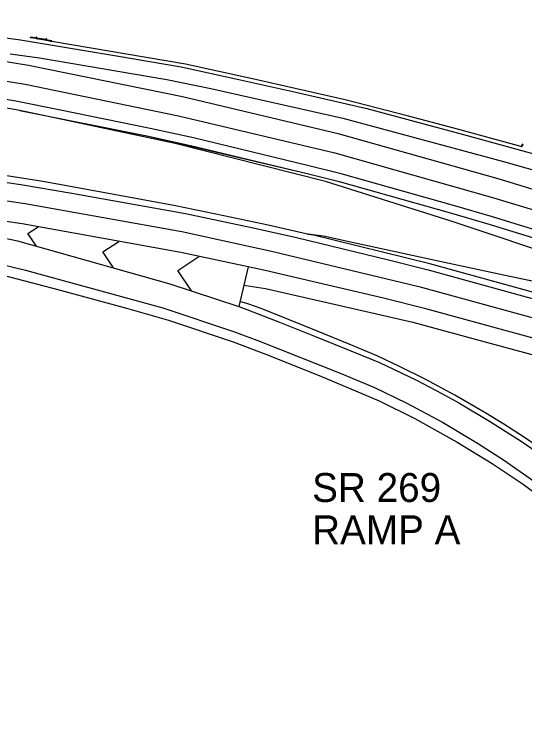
# Model space of a CAD drawing. Extents: x 1855721 to 1876784, y 662259 to 674089.
# Drawn here: x 1874026.9 to 1874344.5, y 669790 to 670235.9 of the extents above; entities that cross this region are included whole.
import ezdxf

# ---------------------------------------------------------------- set-up
doc = ezdxf.new("R2010")
doc.units = 0
for name, color, linetype in [('_CIVIL_CONSTRUCTION', 7, 'Continuous'), ('GE_X_Alignment_100_Bearings', 7, 'Continuous'), ('GE_X_Alignment_100_Cardinal_Points', 7, 'Continuous'), ('GE_X_Alignment_100_Curve_Data', 7, 'Continuous'), ('GE_X_Alignment_100_Distances', 7, 'Continuous'), ('RD_P_Anchor_Assembly', 7, 'Continuous'), ('RD_P_GR_Rt', 7, 'Continuous'), ('SC_Scratch1', 7, 'Continuous')]:
    doc.layers.add(name, color=color, linetype=linetype)

msp = doc.modelspace()

# ---------------------------------------------------------------- linework, layer by layer
at = {"layer": '_CIVIL_CONSTRUCTION'}
msp.add_line((1874172.51, 670078.73), (1874166.57, 670053.98), dxfattribs=at)
for points in [[(1874024.21, 670211.44), (1874042.5, 670208.83), (1874121.86, 670195.43), (1874149.23, 670189.87), (1874231.37, 670171.25), (1874331.43, 670144.39), (1874360.53, 670136.03), (1874385.65, 670128.8), (1874405.39, 670122.67), (1874479.05, 670099.61), (1874543.69, 670077.25), (1874566.95, 670068.66), (1874616.63, 670049.72), (1874641.2, 670039.89), (1874701.25, 670015)], [(1874008.89, 670082.71), (1874033.84, 670076.62), (1874119.31, 670053.19), (1874163.98, 670038.32), (1874179.51, 670032.41), (1874230.65, 670012.2), (1874251.08, 670003.56), (1874270.71, 669994.19), (1874293.29, 669982.11), (1874315.24, 669969.02), (1874331.35, 669958.59), (1874347.94, 669947.07), (1874364.69, 669934.66), (1874379.33, 669923.11), (1874391.51, 669912.94), (1874407.55, 669898.63), (1874421.29, 669885.42), (1874437.51, 669868.5), (1874447.7, 669857.03), (1874462.1, 669839.52), (1874471.05, 669827.84), (1874485.09, 669808.34), (1874501.91, 669783.12)], [(1874656.55, 669923.15), (1874616.51, 669940.01), (1874596.5, 669948.2), (1874520.89, 669977.13), (1874502.63, 669983.85), (1874434.3, 670008.02), (1874411.92, 670015.44), (1874387.2, 670023.2), (1874362.57, 670030.86), (1874283.06, 670052.68), (1874256.59, 670059.19), (1874199.75, 670072.62), (1874183.06, 670076.51), (1874172.51, 670078.73)]]:
    msp.add_lwpolyline(points, dxfattribs=at)
at = {"layer": 'GE_X_Alignment_100_Bearings'}
for points in [[(1873917.88, 670211.07), (1874033.57, 670192.38), (1874128.97, 670172.77), (1874226.34, 670149.67), (1874324.56, 670121.94), (1874380.21, 670105.03), (1874464.42, 670075.97), (1874542.9, 670046.78), (1874613.26, 670018), (1874690.49, 669983.78), (1874745.1, 669957.92), (1874833.48, 669912.76), (1874913.16, 669868.6), (1874975.02, 669831.72), (1875030.09, 669797.13), (1875071.49, 669769.59), (1875139.95, 669721.68), (1875218.25, 669663.57), (1875295.5, 669602.11), (1875347.35, 669557.96), (1875393.18, 669516.35), (1875460.82, 669452.24)], [(1873940.99, 670131.62), (1874033.62, 670118.26), (1874131.15, 670100.65), (1874186.92, 670088.55), (1874278.59, 670066.55), (1874368.65, 670041.87), (1874427.9, 670023.25), (1874517.06, 669991.96), (1874605.73, 669957.51), (1874668.58, 669931.07), (1874758.04, 669889.96), (1874843.89, 669846.49), (1874929.24, 669799.74), (1875003.27, 669755.58), (1875035.18, 669735.37), (1875086.58, 669701.41), (1875161.85, 669649.01), (1875231.41, 669595.91), (1875301.33, 669539.99), (1875372.37, 669478.94), (1875442.56, 669414.34), (1875474.84, 669382.32)]]:
    msp.add_lwpolyline(points, dxfattribs=at)
at = {"layer": 'GE_X_Alignment_100_Cardinal_Points'}
for p, q in [((1874035.4, 670099.57), (1874041.68, 670103.73)), ((1874040.72, 670091.54), (1874035.4, 670099.57)), ((1874082.06, 670088.07), (1874091.92, 670094.6)), ((1874088.69, 670078.06), (1874082.06, 670088.07)), ((1874128.71, 670076.57), (1874141.77, 670085.21)), ((1874137.21, 670063.73), (1874128.71, 670076.57))]:
    msp.add_line(p, q, dxfattribs=at)
msp.add_lwpolyline([(1874172.51, 670078.73), (1874130.43, 670087.6), (1874031.7, 670105.55), (1873940.4, 670118.8), (1873845.62, 670129.61), (1873940.11, 670114.33), (1874028.9, 670094.87), (1874123.7, 670068.22), (1874166.57, 670053.98)], dxfattribs=at)
at = {"layer": 'GE_X_Alignment_100_Curve_Data'}
for points in [[(1874670.21, 669980.46), (1874619.85, 670002.65), (1874584.98, 670017.21), (1874542.37, 670034.53), (1874512.79, 670045.69), (1874466.72, 670062.95), (1874441.32, 670071.81), (1874395.11, 670087.51), (1874370.92, 670095.54), (1874324.54, 670109.9), (1874300.27, 670116.85), (1874230.32, 670136.6), (1874210.28, 670141.71), (1874138.43, 670158.98), (1874111.48, 670164.91), (1874055.63, 670176.31), (1874027.89, 670181.85), (1873932.46, 670197.41)], [(1873959.73, 670140.36), (1874030.99, 670129.99), (1874062.58, 670124.55), (1874133.37, 670112.04), (1874175.53, 670103.13), (1874202.5, 670097.01), (1874259.78, 670083.07), (1874284.46, 670076.94), (1874349.11, 670059.13), (1874393.22, 670046.3), (1874436.95, 670032.51), (1874511.81, 670005.93), (1874548.03, 669992.13), (1874595.43, 669973.68), (1874625.43, 669961.44), (1874654.09, 669949.3)], [(1874166.57, 670053.98), (1874171.68, 670052.29), (1874191.99, 670044.28), (1874213.74, 670035.61), (1874236.42, 670026.56), (1874254.11, 670019.13), (1874277.24, 670008.14), (1874293, 669999.86), (1874303.47, 669994.04), (1874322.68, 669982.7), (1874342.89, 669969.79), (1874361.11, 669957.19)]]:
    msp.add_lwpolyline(points, dxfattribs=at)
at = {"layer": 'GE_X_Alignment_100_Distances'}
msp.add_lwpolyline([(1874696.17, 669994.83), (1874617.96, 670029.04), (1874547.27, 670057.96), (1874468.47, 670087.26), (1874383.91, 670116.45), (1874327.93, 670133.46), (1874229.35, 670161.29), (1874131.56, 670184.49), (1874035.74, 670204.19), (1873919.59, 670222.95), (1873820.41, 670235.94)], dxfattribs=at)
at = {"layer": 'RD_P_Anchor_Assembly'}
for p, q in [((1874036.98, 670221.37), (1874037.02, 670221.61)), ((1874037.86, 670221.21), (1874036.98, 670221.37)), ((1874037.02, 670221.61), (1874037.03, 670221.64)), ((1874050.22, 670219.35), (1874037.03, 670221.64)), ((1874037.06, 670221.59), (1874037.13, 670221.6)), ((1874037.06, 670221.59), (1874037.06, 670221.54)), ((1874037.11, 670221.51), (1874037.06, 670221.54)), ((1874037.11, 670221.51), (1874037.17, 670221.52)), ((1874037.18, 670221.57), (1874037.13, 670221.6)), ((1874037.18, 670221.57), (1874037.17, 670221.52)), ((1874037.35, 670221.52), (1874037.36, 670221.56)), ((1874037.58, 670221.48), (1874037.35, 670221.52)), ((1874037.42, 670221.26), (1874037.42, 670221.26)), ((1874037.58, 670221.48), (1874037.58, 670221.52)), ((1874037.73, 670221.46), (1874037.72, 670221.42)), ((1874037.77, 670221.38), (1874037.72, 670221.42)), ((1874037.73, 670221.46), (1874037.79, 670221.47)), ((1874037.77, 670221.38), (1874037.84, 670221.4)), ((1874037.84, 670221.44), (1874037.79, 670221.47)), ((1874037.84, 670221.44), (1874037.84, 670221.4)), ((1874050.17, 670219.08), (1874037.86, 670221.21)), ((1874040.43, 670221.01), (1874040.44, 670221.05)), ((1874040.66, 670220.97), (1874040.43, 670221.01)), ((1874040.73, 670221.65), (1874040.58, 670221.68)), ((1874040.58, 670221.68), (1874040.58, 670221.65)), ((1874040.62, 670221.71), (1874040.61, 670221.67)), ((1874040.7, 670221.71), (1874040.63, 670221.72)), ((1874040.64, 670221.7), (1874040.64, 670221.67)), ((1874040.65, 670221.75), (1874040.65, 670221.72)), ((1874040.69, 670221.74), (1874040.65, 670221.75)), ((1874040.69, 670221.71), (1874040.65, 670221.72)), ((1874040.66, 670220.97), (1874040.66, 670221.01)), ((1874040.69, 670221.7), (1874040.68, 670221.66)), ((1874040.69, 670221.74), (1874040.69, 670221.71)), ((1874040.71, 670221.69), (1874040.71, 670221.66)), ((1874040.73, 670221.65), (1874040.73, 670221.63)), ((1874041.35, 670221.06), (1874041.34, 670221.05)), ((1874041.34, 670221.05), (1874041.34, 670221.02)), ((1874041.34, 670221.02), (1874041.35, 670221.01)), ((1874041.35, 670221.06), (1874041.35, 670221.01)), ((1874041.48, 670221.04), (1874041.35, 670221.06)), ((1874041.47, 670220.98), (1874041.35, 670221.01)), ((1874041.37, 670221.05), (1874041.36, 670221.02)), ((1874041.38, 670221.05), (1874041.38, 670221)), ((1874041.4, 670221.04), (1874041.39, 670221.01)), ((1874041.42, 670221.05), (1874041.41, 670221)), ((1874041.43, 670221.04), (1874041.42, 670221.01)), ((1874041.45, 670221.04), (1874041.44, 670220.99)), ((1874041.46, 670221.03), (1874041.45, 670221)), ((1874041.48, 670221.05), (1874041.47, 670220.98)), ((1874041.48, 670220.99), (1874041.51, 670220.98)), ((1874041.48, 670220.96), (1874041.51, 670220.96)), ((1874041.49, 670221.03), (1874041.52, 670221.03)), ((1874041.49, 670220.71), (1874041.52, 670220.86)), ((1874042.64, 670220.51), (1874041.49, 670220.71)), ((1874041.53, 670221.1), (1874041.5, 670220.9)), ((1874041.5, 670221.06), (1874041.53, 670221.06)), ((1874041.5, 670220.9), (1874041.53, 670220.9)), ((1874041.53, 670221.06), (1874041.51, 670220.96)), ((1874041.52, 670220.86), (1874041.57, 670221.13)), ((1874041.53, 670221.1), (1874041.56, 670221.1)), ((1874041.54, 670220.97), (1874042.41, 670220.82)), ((1874041.55, 670221.03), (1874042.42, 670220.87)), ((1874041.57, 670221.13), (1874042.71, 670220.93)), ((1874041.6, 670220.79), (1874041.59, 670220.74)), ((1874041.64, 670220.71), (1874041.59, 670220.74)), ((1874041.6, 670220.79), (1874041.66, 670220.8)), ((1874041.64, 670220.71), (1874041.7, 670220.72)), ((1874041.65, 670220.75), (1874041.65, 670220.75)), ((1874041.71, 670220.77), (1874041.66, 670220.8)), ((1874041.71, 670220.77), (1874041.7, 670220.72)), ((1874041.88, 670220.74), (1874041.87, 670220.69)), ((1874041.93, 670220.66), (1874041.87, 670220.69)), ((1874041.88, 670220.74), (1874041.94, 670220.75)), ((1874041.93, 670220.7), (1874041.93, 670220.7)), ((1874041.93, 670220.66), (1874041.99, 670220.67)), ((1874042, 670220.72), (1874041.94, 670220.75)), ((1874042, 670220.72), (1874041.99, 670220.67)), ((1874042.16, 670220.69), (1874042.15, 670220.64)), ((1874042.21, 670220.61), (1874042.15, 670220.64)), ((1874042.16, 670220.69), (1874042.22, 670220.7)), ((1874042.21, 670220.61), (1874042.27, 670220.62)), ((1874042.28, 670220.67), (1874042.22, 670220.7)), ((1874042.22, 670220.66), (1874042.22, 670220.66)), ((1874042.28, 670220.67), (1874042.27, 670220.62)), ((1874046.54, 670220.31), (1874042.41, 670220.82)), ((1874046.55, 670220.36), (1874042.42, 670220.87)), ((1874042.45, 670220.64), (1874042.44, 670220.59)), ((1874042.5, 670220.56), (1874042.44, 670220.59)), ((1874042.45, 670220.64), (1874042.51, 670220.65)), ((1874042.5, 670220.6), (1874042.5, 670220.6)), ((1874042.5, 670220.56), (1874042.56, 670220.57)), ((1874042.57, 670220.62), (1874042.51, 670220.65)), ((1874042.57, 670220.62), (1874042.56, 670220.57)), ((1874042.64, 670220.51), (1874042.67, 670220.67)), ((1874042.67, 670220.67), (1874042.71, 670220.93)), ((1874047.05, 670220.22), (1874046.54, 670220.31)), ((1874047.06, 670220.27), (1874046.55, 670220.36)), ((1874046.59, 670219.94), (1874046.6, 670219.98)), ((1874046.81, 670219.9), (1874046.59, 670219.94)), ((1874046.89, 670220.58), (1874046.74, 670220.61)), ((1874046.74, 670220.61), (1874046.74, 670220.58)), ((1874046.77, 670220.64), (1874046.77, 670220.6)), ((1874046.86, 670220.64), (1874046.79, 670220.65)), ((1874046.8, 670220.63), (1874046.8, 670220.6)), ((1874046.81, 670220.68), (1874046.81, 670220.65)), ((1874046.85, 670220.67), (1874046.81, 670220.68)), ((1874046.84, 670220.64), (1874046.81, 670220.65)), ((1874046.81, 670219.9), (1874046.82, 670219.94)), ((1874046.85, 670220.67), (1874046.84, 670220.64)), ((1874046.84, 670220.63), (1874046.84, 670220.59)), ((1874046.87, 670220.62), (1874046.86, 670220.59)), ((1874046.89, 670220.58), (1874046.89, 670220.56)), ((1874046.97, 670219.92), (1874047.08, 670220.52)), ((1874047, 670219.91), (1874047.1, 670220.52)), ((1874047.08, 670220.22), (1874047.05, 670220.22)), ((1874047.08, 670220.19), (1874047.05, 670220.19)), ((1874047.09, 670220.29), (1874047.06, 670220.3)), ((1874047.09, 670220.26), (1874047.06, 670220.27)), ((1874047.09, 670220.2), (1874047.11, 670220.27)), ((1874047.17, 670220.19), (1874047.09, 670220.2)), ((1874047.18, 670220.26), (1874047.11, 670220.27)), ((1874047.11, 670220.2), (1874047.12, 670220.27)), ((1874047.13, 670220.22), (1874047.13, 670220.24)), ((1874047.14, 670220.19), (1874047.15, 670220.27)), ((1874047.16, 670220.21), (1874047.16, 670220.24)), ((1874047.17, 670220.19), (1874047.18, 670220.26)), ((1874047.17, 670220.19), (1874047.18, 670220.2)), ((1874047.19, 670220.25), (1874047.18, 670220.26)), ((1874047.18, 670220.2), (1874047.19, 670220.25)), ((1874048.99, 670219.48), (1874049, 670219.5)), ((1874048.99, 670219.48), (1874049.28, 670219.25)), ((1874049, 670219.5), (1874049.19, 670219.34)), ((1874049.28, 670219.25), (1874050.18, 670219.09)), ((1874049.32, 670219.52), (1874049.3, 670219.39)), ((1874049.32, 670219.52), (1874050.22, 670219.36)), ((1874049.4, 670219.44), (1874049.39, 670219.4)), ((1874049.45, 670219.37), (1874049.39, 670219.4)), ((1874049.4, 670219.44), (1874049.46, 670219.46)), ((1874049.41, 670219.38), (1874049.42, 670219.38)), ((1874049.42, 670219.45), (1874049.43, 670219.45)), ((1874049.45, 670219.37), (1874049.51, 670219.38)), ((1874049.52, 670219.42), (1874049.46, 670219.46)), ((1874049.46, 670219.41), (1874049.46, 670219.41)), ((1874049.48, 670219.37), (1874049.49, 670219.37)), ((1874049.49, 670219.44), (1874049.5, 670219.44)), ((1874049.52, 670219.42), (1874049.51, 670219.38)), ((1874049.68, 670219.41), (1874049.68, 670219.45)), ((1874049.9, 670219.37), (1874049.68, 670219.41)), ((1874049.9, 670219.37), (1874049.9, 670219.41)), ((1874050.02, 670219.34), (1874050.01, 670219.29)), ((1874050.06, 670219.26), (1874050.01, 670219.29)), ((1874050.02, 670219.34), (1874050.08, 670219.35)), ((1874050.02, 670219.28), (1874050.04, 670219.27)), ((1874050.03, 670219.35), (1874050.05, 670219.34)), ((1874050.06, 670219.26), (1874050.12, 670219.27)), ((1874050.07, 670219.3), (1874050.07, 670219.3)), ((1874050.13, 670219.32), (1874050.08, 670219.35)), ((1874050.09, 670219.26), (1874050.11, 670219.26)), ((1874050.1, 670219.33), (1874050.12, 670219.33)), ((1874050.13, 670219.32), (1874050.12, 670219.27)), ((1874050.17, 670219.08), (1874050.22, 670219.35)), ((1874342.53, 670153.58), (1874342.54, 670153.6)), ((1874342.85, 670153.49), (1874342.53, 670153.58)), ((1874342.69, 670153.55), (1874342.54, 670153.6)), ((1874342.88, 670155.01), (1874342.6, 670154.06)), ((1874342.65, 670154.03), (1874342.61, 670154.05)), ((1874342.65, 670154.06), (1874342.65, 670154.03)), ((1874343, 670153.96), (1874342.65, 670154.06)), ((1874342.66, 670154.04), (1874342.67, 670154.05)), ((1874342.81, 670153.99), (1874342.66, 670154.04)), ((1874342.98, 670153.96), (1874342.67, 670154.05)), ((1874342.69, 670153.55), (1874342.81, 670153.99)), ((1874342.7, 670153.55), (1874342.83, 670153.99)), ((1874342.85, 670153.51), (1874342.7, 670153.55)), ((1874342.98, 670153.94), (1874342.83, 670153.99)), ((1874342.84, 670153.98), (1874342.84, 670153.97)), ((1874342.99, 670153.93), (1874342.84, 670153.97)), ((1874342.87, 670153.96), (1874342.85, 670153.91)), ((1874342.85, 670153.49), (1874342.85, 670153.51)), ((1874342.86, 670153.87), (1874342.89, 670153.99)), ((1874342.93, 670153.88), (1874342.86, 670153.9)), ((1874342.92, 670153.85), (1874342.86, 670153.87)), ((1874343.31, 670154.9), (1874342.89, 670155.02)), ((1874343.17, 670154.94), (1874342.89, 670153.99)), ((1874342.92, 670153.85), (1874342.95, 670153.97)), ((1874343.23, 670154.92), (1874342.95, 670153.97)), ((1874342.96, 670153.93), (1874342.95, 670153.89)), ((1874342.98, 670153.94), (1874342.98, 670153.96)), ((1874343, 670153.96), (1874342.99, 670153.93)), ((1874342.99, 670153.94), (1874342.99, 670153.93)), ((1874343.03, 670153.92), (1874342.99, 670153.93)), ((1874343.32, 670154.89), (1874343.04, 670153.93))]:
    msp.add_line(p, q, dxfattribs=at)
for points in [[(1874040.88, 670221.61), (1874040.43, 670221.69), (1874040.32, 670221.07), (1874040.77, 670220.99)], [(1874047.04, 670220.54), (1874046.59, 670220.62), (1874046.48, 670220), (1874046.93, 670219.92)]]:
    msp.add_lwpolyline(points, close=True, dxfattribs=at)
for centre, radius, start, end in [((1874040.63, 670221.71), 0.0139, 350.1433, 170.1433), ((1874040.66, 670221.69), 0.0211, 350.1433, 170.1433), ((1874040.7, 670221.69), 0.0139, 350.1433, 170.1433), ((1874041.49, 670221.01), 0.0224, 80.1433, 260.1433), ((1874041.48, 670220.98), 0.0148, 80.1433, 260.1433), ((1874041.49, 670221.05), 0.0148, 80.1433, 260.1433), ((1874046.79, 670220.64), 0.0139, 350.1433, 170.1433), ((1874046.82, 670220.62), 0.0211, 350.1433, 170.1433), ((1874046.86, 670220.62), 0.0139, 350.1433, 170.1433), ((1874049.23, 670219.39), 0.067, 234.9053, 354.9053), ((1874049.41, 670219.42), 0.0348, 80.1433, 260.1433), ((1874049.5, 670219.4), 0.0348, 260.1433, 80.1433), ((1874050.03, 670219.31), 0.0348, 80.1433, 260.1433), ((1874050.11, 670219.3), 0.0348, 260.1433, 80.1433), ((1874342.61, 670154.06), 0.01, 163.8689, 253.8689), ((1874342.89, 670155.01), 0.01, 73.8689, 163.8689), ((1874343.03, 670153.93), 0.01, 253.8689, 343.8689), ((1874343.31, 670154.89), 0.01, 343.8689, 73.8689)]:
    msp.add_arc(centre, radius, start, end, dxfattribs=at)
for centre, major_axis in [((1874037.12, 670221.55), (-0.0565, 0.0098)), ((1874037.12, 670221.55), (-0.0343, 0.006)), ((1874037.78, 670221.43), (-0.0565, 0.0098)), ((1874037.78, 670221.43), (-0.0343, 0.006)), ((1874041.65, 670220.75), (-0.0565, 0.0098)), ((1874041.65, 670220.75), (-0.0343, 0.006)), ((1874041.93, 670220.7), (-0.0565, 0.0098)), ((1874041.93, 670220.7), (-0.0343, 0.006)), ((1874042.22, 670220.66), (-0.0565, 0.0098)), ((1874042.22, 670220.66), (-0.0343, 0.006)), ((1874042.5, 670220.6), (-0.0565, 0.0098)), ((1874042.5, 670220.6), (-0.0343, 0.006)), ((1874049.46, 670219.41), (-0.0565, 0.0098)), ((1874049.46, 670219.41), (-0.0343, 0.006)), ((1874050.07, 670219.3), (-0.0565, 0.0098)), ((1874050.07, 670219.3), (-0.0343, 0.006))]:
    msp.add_ellipse(centre, major_axis=major_axis, ratio=0.66, dxfattribs=at)
for centre, major_axis, ratio, start_param, end_param in [((1874037.46, 670221.51), (-0.0094, -0.0544), 0.944544, 4.795036, 7.771335), ((1874040.54, 670221), (-0.0094, -0.0544), 0.944544, 4.924146, 7.64222), ((1874041.61, 670220.76), (-0.0343, 0.006), 0.66, 5.188505, 7.377866), ((1874041.69, 670220.75), (0.0343, -0.006), 0.66, 5.188511, 7.377859), ((1874041.89, 670220.71), (-0.0343, 0.006), 0.66, 5.188505, 7.377866), ((1874041.98, 670220.7), (0.0343, -0.006), 0.66, 5.188511, 7.377859), ((1874042.17, 670220.66), (-0.0343, 0.006), 0.66, 5.188505, 7.377866), ((1874042.26, 670220.65), (0.0343, -0.006), 0.66, 5.188511, 7.377859), ((1874042.46, 670220.61), (-0.0343, 0.006), 0.66, 5.188505, 7.377866), ((1874042.55, 670220.6), (0.0343, -0.006), 0.66, 5.188511, 7.377859), ((1874046.7, 670219.93), (-0.0094, -0.0544), 0.944544, 4.924146, 7.64222), ((1874047.08, 670220.24), (-0.0041, -0.0236), 0.944544, 0.365065, 2.776616), ((1874047.08, 670220.2), (-0.0025, -0.0145), 0.944544, 6.200625, 9.468001), ((1874047.09, 670220.28), (-0.0025, -0.0145), 0.944544, 6.200625, 9.468001), ((1874049.78, 670219.4), (-0.0094, -0.0544), 0.944544, 4.924146, 7.64222), ((1874342.86, 670153.91), (0.0039, 0.0134), 0.929688, 1.586202, 2.897406), ((1874342.93, 670153.89), (0.0039, 0.0134), 0.929688, 3.345604, 4.722982), ((1874343.2, 670154.93), (-0.1, 0.029), 0.312583, 3.061844, 6.362934)]:
    msp.add_ellipse(centre, major_axis=major_axis, ratio=ratio, start_param=start_param, end_param=end_param, dxfattribs=at)
at = {"layer": 'RD_P_GR_Rt'}
msp.add_lwpolyline([(1874342.85, 670153.49), (1874300.51, 670165.14), (1874272.23, 670172.49), (1874232.84, 670182.81), (1874176.92, 670195.34), (1874133.39, 670204.88), (1874050.17, 670219.08)], dxfattribs=at)
at = {"layer": 'SC_Scratch1'}
for points in [[(1873954.55, 670230.14), (1874030.65, 670220.12), (1874090.4, 670210.17), (1874130.75, 670203.28), (1874166.7, 670195.46), (1874202.16, 670187.57), (1874246.18, 670177.22), (1874306.5, 670161.15), (1874347.83, 670149.82), (1874388.44, 670138.06), (1874426.7, 670126.12), (1874467.64, 670113.31), (1874501.58, 670102.05), (1874544.17, 670087.36), (1874580.55, 670073.82), (1874611.63, 670061.89), (1874649.03, 670046.73)], [(1874373.9, 670082.06), (1874298.84, 670107.25), (1874220.6, 670131.78), (1874181.92, 670141.6), (1874127, 670155.54), (1874071.58, 670167.3), (1874029.34, 670176.2), (1873987, 670183.51)], [(1874030.22, 670176.05), (1874110.45, 670160.07), (1874137.32, 670154.17), (1874209.09, 670136.91), (1874229.04, 670131.83), (1874298.92, 670112.1), (1874323.12, 670105.16), (1874369.41, 670090.83), (1874393.54, 670082.83), (1874439.71, 670067.13), (1874465.03, 670058.3), (1874511.05, 670041.07), (1874540.57, 670029.92), (1874583.09, 670012.64), (1874617.9, 669998.11), (1874668.2, 669975.95), (1874687.91, 669967.1), (1874728.48, 669947.65), (1874744.65, 669939.73), (1874821.87, 669900.37), (1874844.72, 669887.87), (1874965.87, 669815.96)], [(1874373.9, 670082.06), (1874298.84, 670107.25), (1874220.6, 670131.78), (1874181.92, 670141.6), (1874127, 670155.54), (1874030.22, 670176.05), (1874110.45, 670160.07), (1874209.09, 670136.91), (1874229.04, 670131.83), (1874298.92, 670112.1), (1874323.12, 670105.16), (1874369.41, 670090.83)], [(1874018.23, 670136.26), (1874045.93, 670131.87), (1874087.83, 670124.19), (1874127.15, 670116.99), (1874157.26, 670110.75), (1874184.85, 670104.85), (1874209.36, 670099.22), (1874219.41, 670098.03), (1874235.34, 670094.56), (1874291.62, 670082.33), (1874335.37, 670073.04), (1874372.14, 670065.23)], [(1874350.13, 670062.75), (1874285.41, 670080.58), (1874211.38, 670098.98), (1874209.51, 670099.18), (1874219.41, 670098.03), (1874235.34, 670094.56), (1874291.62, 670082.33), (1874335.37, 670073.04), (1874375.81, 670064.45)], [(1874858.4, 669856.13), (1874775.3, 669898.11), (1874739.64, 669914.94), (1874704.64, 669930.94), (1874655.59, 669952.75), (1874626.88, 669964.91), (1874596.83, 669977.18), (1874549.38, 669995.65), (1874513.11, 670009.46), (1874438.15, 670036.08), (1874394.31, 670049.9), (1874350.13, 670062.75), (1874285.41, 670080.58), (1874211.38, 670098.98)], [(1874015.74, 670074.56), (1874053.9, 670064.63), (1874096.72, 670052.99), (1874122.85, 670045.57), (1874163.13, 670032.13), (1874183.78, 670024.09), (1874216.63, 670011.14), (1874254.01, 669995.4), (1874276.18, 669984.31), (1874302.5, 669969.62), (1874324.29, 669956.27), (1874343.6, 669943.38), (1874370.63, 669923.23), (1874388.8, 669908.16), (1874414.45, 669884.65), (1874430.87, 669867.96), (1874454.33, 669840.89), (1874478.41, 669808.15), (1874498.8, 669776.52)], [(1874169.78, 670067.38), (1874183.16, 670065.22), (1874252.32, 670049.52), (1874274.85, 670044.4), (1874321.39, 670031.65), (1874354.29, 670022.63), (1874382.29, 670014.09), (1874410.38, 670005.18), (1874449.52, 669991.93), (1874504.31, 669972.92), (1874540.14, 669959.25), (1874576.33, 669945.26), (1874603.98, 669934.39), (1874638.27, 669919.9), (1874663.63, 669909.02)], [(1874362.56, 669960.15), (1874343.83, 669972.92), (1874331.46, 669980.8), (1874320.32, 669987.59), (1874301.01, 669998.76), (1874282.65, 670008.73), (1874267.1, 670016.59), (1874253.18, 670023.08), (1874235.24, 670030.63), (1874215.93, 670038.42), (1874196.44, 670046.29), (1874181.47, 670052.34), (1874176.95, 670054.15), (1874172.31, 670055.68), (1874167.34, 670057.22)]]:
    msp.add_lwpolyline(points, dxfattribs=at)

# ---------------------------------------------------------------- texts
for s, p in [('SR 269', (1874212.23, 669932.38)), ('RAMP A', (1874212.23, 669906.04))]:
    msp.add_text(s, height=18, dxfattribs=at).set_placement(p)

doc.saveas('drawing.dxf')
